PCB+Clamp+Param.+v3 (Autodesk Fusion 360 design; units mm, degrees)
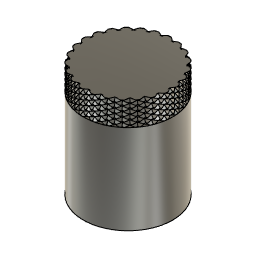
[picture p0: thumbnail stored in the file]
sketch "Sketch1" plane through (0, 0, 0) normal (0, 0, 1) x axis (1, 0, 0)
  circle C1 centre (0, 0) radius 7.5
  circle C2 centre (0, 0) radius 3.175
  point P1 (0, 0)
  point P2 (0, 0)
  coincident P1 P2
  concentric C1 C2
  dimension "d1" diameter C1 = 15
  dimension "d2" diameter C2 = 6.35
extrude "Extrude1" new body sketch "Sketch1" along normal blind 15
hole "Hole1" HoleDepth 5 HoleDiameter 5.118 TipAngle 180
ground "Ground1"
ground "Ground2"
extrude "Extrude1" sketch "Sketch1" blind 4 named "d11"
extrude "Extrude2" sketch "Sketch1" profile of C2 blind -5
thread "Thread1"
coil_primitive "CoilPrimitive1" Diameter 15 SectionSize 1 TaperAngle 0 Revolutions 0.2 Height -4 (= "-d11")
mirror "Mirror1" mirrorStitchTolerance 0.1
circular_pattern "C-Pattern1" countU 25 TotalAngle 360
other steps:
thread "Thread1"
create_component "CreateComponent1"
create_component "CreateComponent2"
